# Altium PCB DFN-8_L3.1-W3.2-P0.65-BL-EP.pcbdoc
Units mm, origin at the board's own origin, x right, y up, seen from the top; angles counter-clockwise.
Board outline 15.76 x 16.6 mm, 2 copper layers (Top Layer, Bottom Layer), stack 0 mm thick; 1 components, 0 nets, 10 pads, 0 vias.
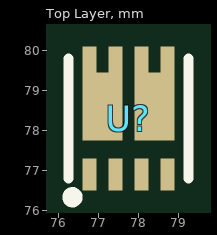
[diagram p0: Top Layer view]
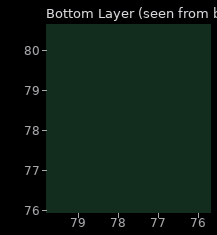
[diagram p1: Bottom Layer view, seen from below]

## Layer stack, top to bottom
Top Layer: signal copper (thickness not stored)
Bottom Layer: signal copper (thickness not stored)

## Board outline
85.61,69.85 69.85,69.85 69.85,86.447 85.61,86.447

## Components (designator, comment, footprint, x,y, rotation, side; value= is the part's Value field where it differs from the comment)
U? "" DFN-8_L3.1-W3.2-P0.65-BL-EP 77.76,78.297 r0 top

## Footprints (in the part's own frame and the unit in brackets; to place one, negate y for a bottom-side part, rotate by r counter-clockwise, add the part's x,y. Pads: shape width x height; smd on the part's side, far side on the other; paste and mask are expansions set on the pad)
DFN-8_L3.1-W3.2-P0.65-BL-EP [mm]
  rect 0.35x0.8 smd paste-100 mask+0.051: 1(-0.97,-1.399) 2(-0.32,-1.399) 3(0.33,-1.399) 4(0.97,-1.399) 5(0.97,1.399) 6(0.33,1.399) 7(-0.32,1.399) 8(-0.97,1.399)
  rect 1x1.7 smd paste-100 mask+0.051: 6(0.65,0.3) 8(-0.65,0.3)
  silkscreen extent -1.53,-2.1 1.5,1.5

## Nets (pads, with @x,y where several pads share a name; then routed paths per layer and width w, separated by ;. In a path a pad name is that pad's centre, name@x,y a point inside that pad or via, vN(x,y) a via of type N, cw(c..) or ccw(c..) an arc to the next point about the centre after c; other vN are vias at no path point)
pads on no net: U?.1 U?.2 U?.3 U?.4 U?.5 U?.6 U?.7 U?.8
